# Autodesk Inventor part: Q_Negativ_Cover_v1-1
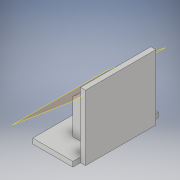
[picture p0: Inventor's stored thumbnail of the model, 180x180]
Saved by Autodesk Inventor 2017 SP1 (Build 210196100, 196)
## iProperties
Part Number: Q_Negativ_Cover_v1-1
Material: Generisch
Document SubType Name: Modeling
Designer: haesner
Density: 1 g/cm^3
Appearance: Vorgabe
Part Number: Q_Negativ_Cover_v1-1_3D-Druck
Author: haesner
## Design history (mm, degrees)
sketch "Skizze2"
  geometry: L1 (0, 17)-(0, -17); L2 (0, -23.8)-(0, 23.8) reference; L3 (0, 17)-(-16, 17); L4 (-16, 17)-(-16, -17); L5 (-16, -17)-(0, -17); L6 (-19.2, 0)-(3.2, 0) reference; 1 further point
  constraints: 8 end point, 1 collinear, 1 horizontal, 1 parallel, 1 perpendicular, 1 vertical, 1 other
  dimensions: "d21" = 34 distance of L1.start L1.end; "d22" = 16 distance of L1.start L3.end
extrude "Extrusion1" new body sketch "Skizze2" distance "d1" = 2; taper "d2" = 0 deg
sketch "Skizze3"
  geometry: L1 (0, -17)-(0, 17) reference; L2 (0, 8.5)-(-8.5, 8.5); L3 (-8.5, 8.5)-(-8.5, -8.5); L4 (-8.5, -8.5)-(0, -8.5); L5 (0, -8.5)-(0, 8.5); L6 (-19.2, 0)-(3.2, 0) reference; 1 further point
  constraints: 8 end point, 2 parallel, 1 horizontal, 1 perpendicular, 1 point on line, 1 other
  dimensions: "d3" = 17 distance between parallel lines of L4 L2; "d4" = 8.5 distance between parallel lines of L3 L1
extrude "Extrusion2" join sketch "Skizze3" distance "d5" = 21; taper "d6" = 0 deg
workplane "Arbeitsebene1"
feature "Trennen1"
sketch "Skizze4"
  geometry: L1 (0, 31)-(-26, 31); L2 (-26, 31)-(-26, 3); L3 (-26, 3)-(0, 3); L4 (0, 3)-(0, 31); L5 (0, -6.8)-(0, 40.8) reference; L6 (5.2, 17)-(-31.2, 17) reference; L7 (0, 34)-(0, 0) reference; 1 further point
  constraints: 8 end point, 2 parallel, 1 collinear, 1 horizontal, 1 perpendicular, 1 other
  dimensions: "d8" = 28 distance between parallel lines of L3 L1; "d9" = 26 distance between parallel lines of L2 L4
extrude "Extrusion3" join sketch "Skizze4" distance "d10" = 2; taper "d11" = 0 deg
node "Volumenkörper1"
other parameters: "d7" = -40 deg
